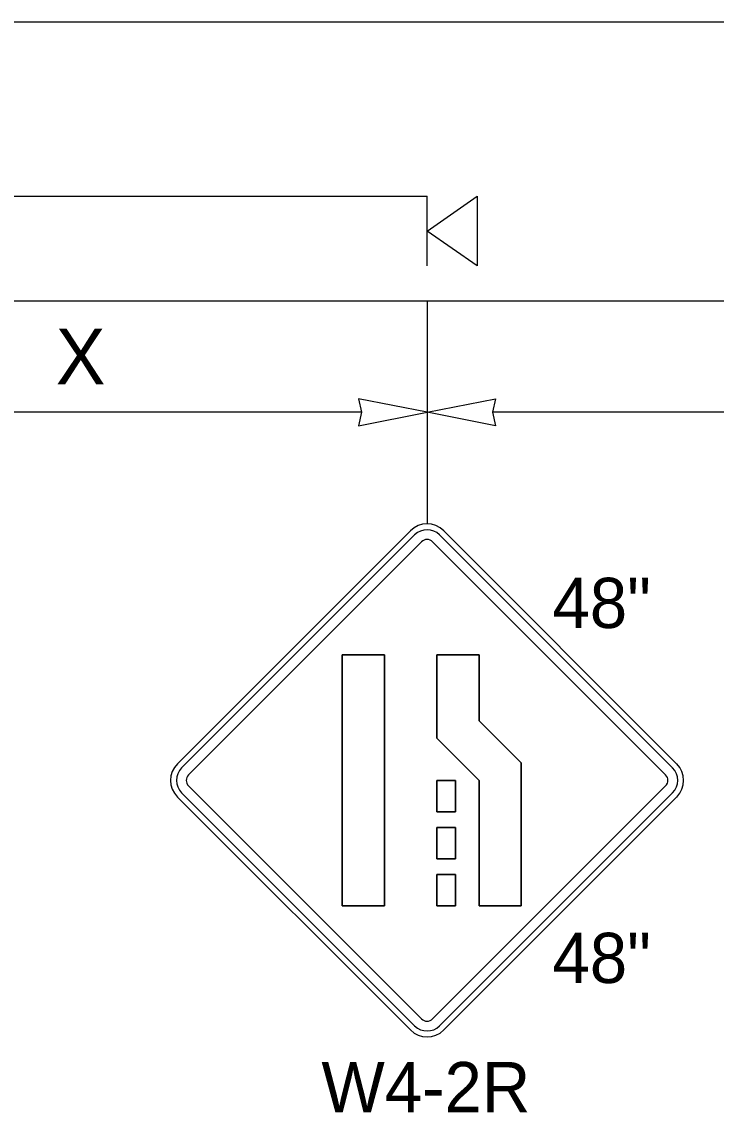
# Model space of a CAD drawing. Extents: x 99958 to 100176, y 99935 to 100011.
# Drawn here: x 100004.182 to 100005.178, y 99943.572 to 99945.136 of the extents above; entities that cross this region are included whole.
import ezdxf

# ---------------------------------------------------------------- set-up
doc = ezdxf.new("R2010")
doc.units = 0
for name, color, linetype in [('RD_ED_ShoulderPavedEdge', 7, 'Continuous'), ('RD_MK_LineEdgeWhite', 7, 'Continuous'), ('TR_SN_ConstructionSigns', 7, 'Continuous'), ('TR_WZ_PortableSignMountBlk-Org', 7, 'Continuous'), ('TR_WZ_WorkZoneDetails', 7, 'Continuous'), ('TR_WZ_WorkZoneTextCurrent', 7, 'Continuous')]:
    doc.layers.add(name, color=color, linetype=linetype)

msp = doc.modelspace()

# ---------------------------------------------------------------- linework, layer by layer
at = {"layer": 'RD_ED_ShoulderPavedEdge'}
msp.add_line((100000.8283, 99944.7357), (100014.8933, 99944.7357), dxfattribs=at)
at = {"layer": 'RD_MK_LineEdgeWhite'}
msp.add_line((100000.8283, 99945.1357), (100014.8933, 99945.1357), dxfattribs=at)
at = {"layer": 'TR_SN_ConstructionSigns'}
for p, q in [((100004.7397, 99944.4058), (100004.4056, 99944.0717)), ((100004.7457, 99944.3999), (100004.4116, 99944.0658)), ((100005.1156, 99944.0658), (100004.7815, 99944.3999)), ((100005.1215, 99944.0717), (100004.7874, 99944.4058)), ((100004.4215, 99944.0558), (100004.7556, 99944.3899)), ((100004.7715, 99944.3899), (100005.1056, 99944.0558)), ((100004.6419, 99944.2279), (100004.7024, 99944.2279)), ((100004.6419, 99943.8679), (100004.6419, 99944.2279)), ((100004.7024, 99944.2279), (100004.6419, 99944.2279)), ((100004.6419, 99944.2279), (100004.6419, 99943.8679)), ((100004.7024, 99944.2279), (100004.7024, 99943.8679)), ((100004.7024, 99943.8679), (100004.7024, 99944.2279)), ((100004.7776, 99944.2279), (100004.8381, 99944.2279)), ((100004.7776, 99944.1083), (100004.7776, 99944.2279)), ((100004.8381, 99944.2279), (100004.7776, 99944.2279)), ((100004.7776, 99944.2279), (100004.7776, 99944.1083)), ((100004.8381, 99944.2279), (100004.8381, 99944.1334)), ((100004.8381, 99944.1334), (100004.8381, 99944.2279)), ((100004.8381, 99944.1334), (100004.8986, 99944.0729)), ((100004.8986, 99944.0729), (100004.8381, 99944.1334)), ((100004.8381, 99944.0479), (100004.7776, 99944.1083)), ((100004.7776, 99944.1083), (100004.8381, 99944.0479)), ((100004.8986, 99944.0729), (100004.8986, 99943.8679)), ((100004.8986, 99943.8679), (100004.8986, 99944.0729)), ((100004.7776, 99944.0479), (100004.8044, 99944.0479)), ((100004.7776, 99944.0029), (100004.7776, 99944.0479)), ((100004.8044, 99944.0479), (100004.7776, 99944.0479)), ((100004.7776, 99944.0479), (100004.7776, 99944.0029)), ((100004.8044, 99944.0479), (100004.8044, 99944.0029)), ((100004.8044, 99944.0029), (100004.8044, 99944.0479)), ((100004.8381, 99943.8679), (100004.8381, 99944.0479)), ((100004.8381, 99944.0479), (100004.8381, 99943.8679)), ((100004.4116, 99944.03), (100004.7457, 99943.6959)), ((100004.7556, 99943.7058), (100004.4215, 99944.0399)), ((100005.1056, 99944.0399), (100004.7715, 99943.7058)), ((100004.7815, 99943.6959), (100005.1156, 99944.03)), ((100004.4056, 99944.024), (100004.7397, 99943.6899)), ((100004.7874, 99943.6899), (100005.1215, 99944.024)), ((100004.8044, 99944.0029), (100004.7776, 99944.0029)), ((100004.7776, 99944.0029), (100004.8044, 99944.0029)), ((100004.7776, 99943.9804), (100004.8044, 99943.9804)), ((100004.7776, 99943.9354), (100004.7776, 99943.9804)), ((100004.8044, 99943.9804), (100004.7776, 99943.9804)), ((100004.7776, 99943.9804), (100004.7776, 99943.9354)), ((100004.8044, 99943.9804), (100004.8044, 99943.9354)), ((100004.8044, 99943.9354), (100004.8044, 99943.9804)), ((100004.8044, 99943.9354), (100004.7776, 99943.9354)), ((100004.7776, 99943.9354), (100004.8044, 99943.9354)), ((100004.7776, 99943.9129), (100004.8044, 99943.9129)), ((100004.7776, 99943.8679), (100004.7776, 99943.9129)), ((100004.8044, 99943.9129), (100004.7776, 99943.9129)), ((100004.7776, 99943.9129), (100004.7776, 99943.8679)), ((100004.8044, 99943.9129), (100004.8044, 99943.8679)), ((100004.8044, 99943.8679), (100004.8044, 99943.9129)), ((100004.7024, 99943.8679), (100004.6419, 99943.8679)), ((100004.6419, 99943.8679), (100004.7024, 99943.8679)), ((100004.8044, 99943.8679), (100004.7776, 99943.8679)), ((100004.7776, 99943.8679), (100004.8044, 99943.8679)), ((100004.8986, 99943.8679), (100004.8381, 99943.8679)), ((100004.8381, 99943.8679), (100004.8986, 99943.8679))]:
    msp.add_line(p, q, dxfattribs=at)
for centre, radius, start, end in [((100004.7636, 99944.382), 0.0338, 45, 135), ((100004.7636, 99944.382), 0.0253, 45, 135), ((100004.7636, 99944.382), 0.0113, 45, 135), ((100004.4295, 99944.0479), 0.0338, 135, 225), ((100005.0977, 99944.0479), 0.0338, 315, 45), ((100004.4295, 99944.0479), 0.0253, 135, 225), ((100004.4295, 99944.0479), 0.0113, 135, 225), ((100005.0977, 99944.0479), 0.0113, 315, 45), ((100005.0977, 99944.0479), 0.0253, 315, 45), ((100004.7636, 99943.7138), 0.0113, 225, 315), ((100004.7636, 99943.7138), 0.0338, 225, 315), ((100004.7636, 99943.7138), 0.0253, 225, 315)]:
    msp.add_arc(centre, radius, start, end, dxfattribs=at)
at = {"layer": 'TR_WZ_PortableSignMountBlk-Org'}
msp.add_line((100004.7636, 99944.7858), (100004.7636, 99944.8858), dxfattribs=at)
msp.add_lwpolyline([(100004.7636, 99944.8357), (100004.8354, 99944.8858), (100004.8354, 99944.7858)], close=True, dxfattribs=at)
at = {"layer": 'TR_WZ_WorkZoneDetails'}
for p, q in [((100002.2354, 99944.8858), (100004.7636, 99944.8858)), ((100004.7636, 99944.736), (100004.7636, 99944.4157)), ((100004.6698, 99944.5757), (100003.8573, 99944.5757)), ((100005.6698, 99944.5757), (100004.8573, 99944.5757))]:
    msp.add_line(p, q, dxfattribs=at)
for points in [[(100004.7636, 99944.5757), (100004.6653, 99944.595), (100004.6698, 99944.5757), (100004.6653, 99944.5565)], [(100004.7636, 99944.5757), (100004.8619, 99944.595), (100004.8573, 99944.5757), (100004.8619, 99944.5565)]]:
    msp.add_lwpolyline(points, close=True, dxfattribs=at)

# ---------------------------------------------------------------- texts
at = {"layer": 'TR_SN_ConstructionSigns'}
for s, p in [('48"', (100004.9434, 99944.2664)), ('48"', (100004.9434, 99943.7573)), ('W4-2R', (100004.6121, 99943.572))]:
    msp.add_text(s, height=0.072, rotation=360, dxfattribs=at).set_placement(p)
at = {"layer": 'TR_WZ_WorkZoneTextCurrent'}
msp.add_text('X', height=0.08, rotation=360, dxfattribs=at).set_placement((100004.2311, 99944.6157))

doc.saveas('drawing.dxf')
